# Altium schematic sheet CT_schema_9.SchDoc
size 146 x 119 mm
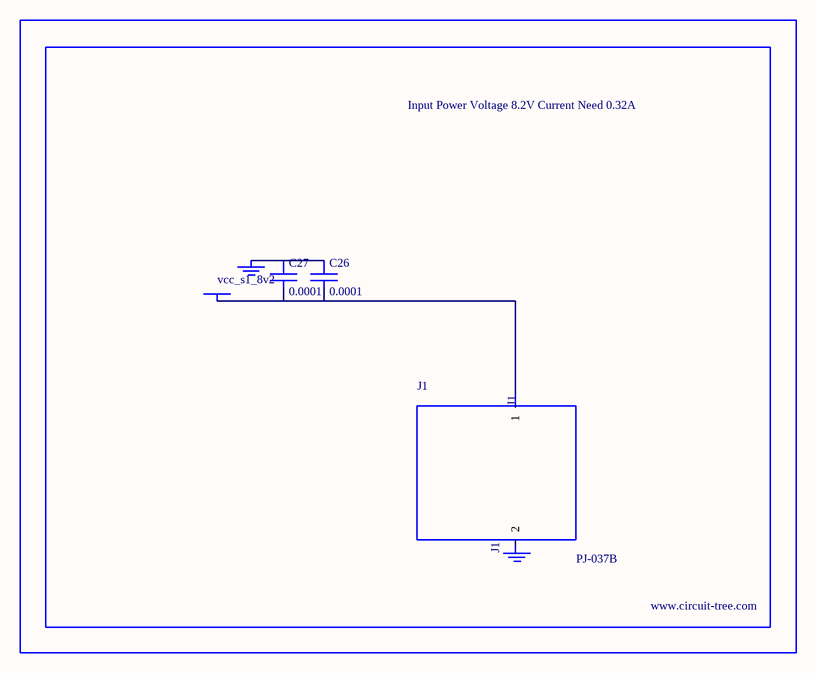
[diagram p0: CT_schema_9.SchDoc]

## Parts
BORDER8  (no value)
C26  0.0001  [EXV-9H]
C27  0.0001  [EXV-9H]
GND_INSTANCE_8_0  (no value)
GND_INSTANCE_8_1  (no value)
J1  PJ-037B  [PJ-037B_PACKAGE]
POWER_INSTANCE_8_0  vcc_s1_8v2

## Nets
NetC26_1: C26.1 C27.1 GND_INSTANCE_8_0.0(GND)
NetC26_2: C26.2 C27.2 J1.1 POWER_INSTANCE_8_0.0(PWR)

Not connected (* = marked no-connect by the designer): GND_INSTANCE_8_1 0(GND); J1 2

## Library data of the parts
BORDER8 = BORDER_PAGE8
C26 C27 = EDK107M035A9HAA
GND_INSTANCE_8_0 GND_INSTANCE_8_1 = GND
POWER_INSTANCE_8_0 = PWR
